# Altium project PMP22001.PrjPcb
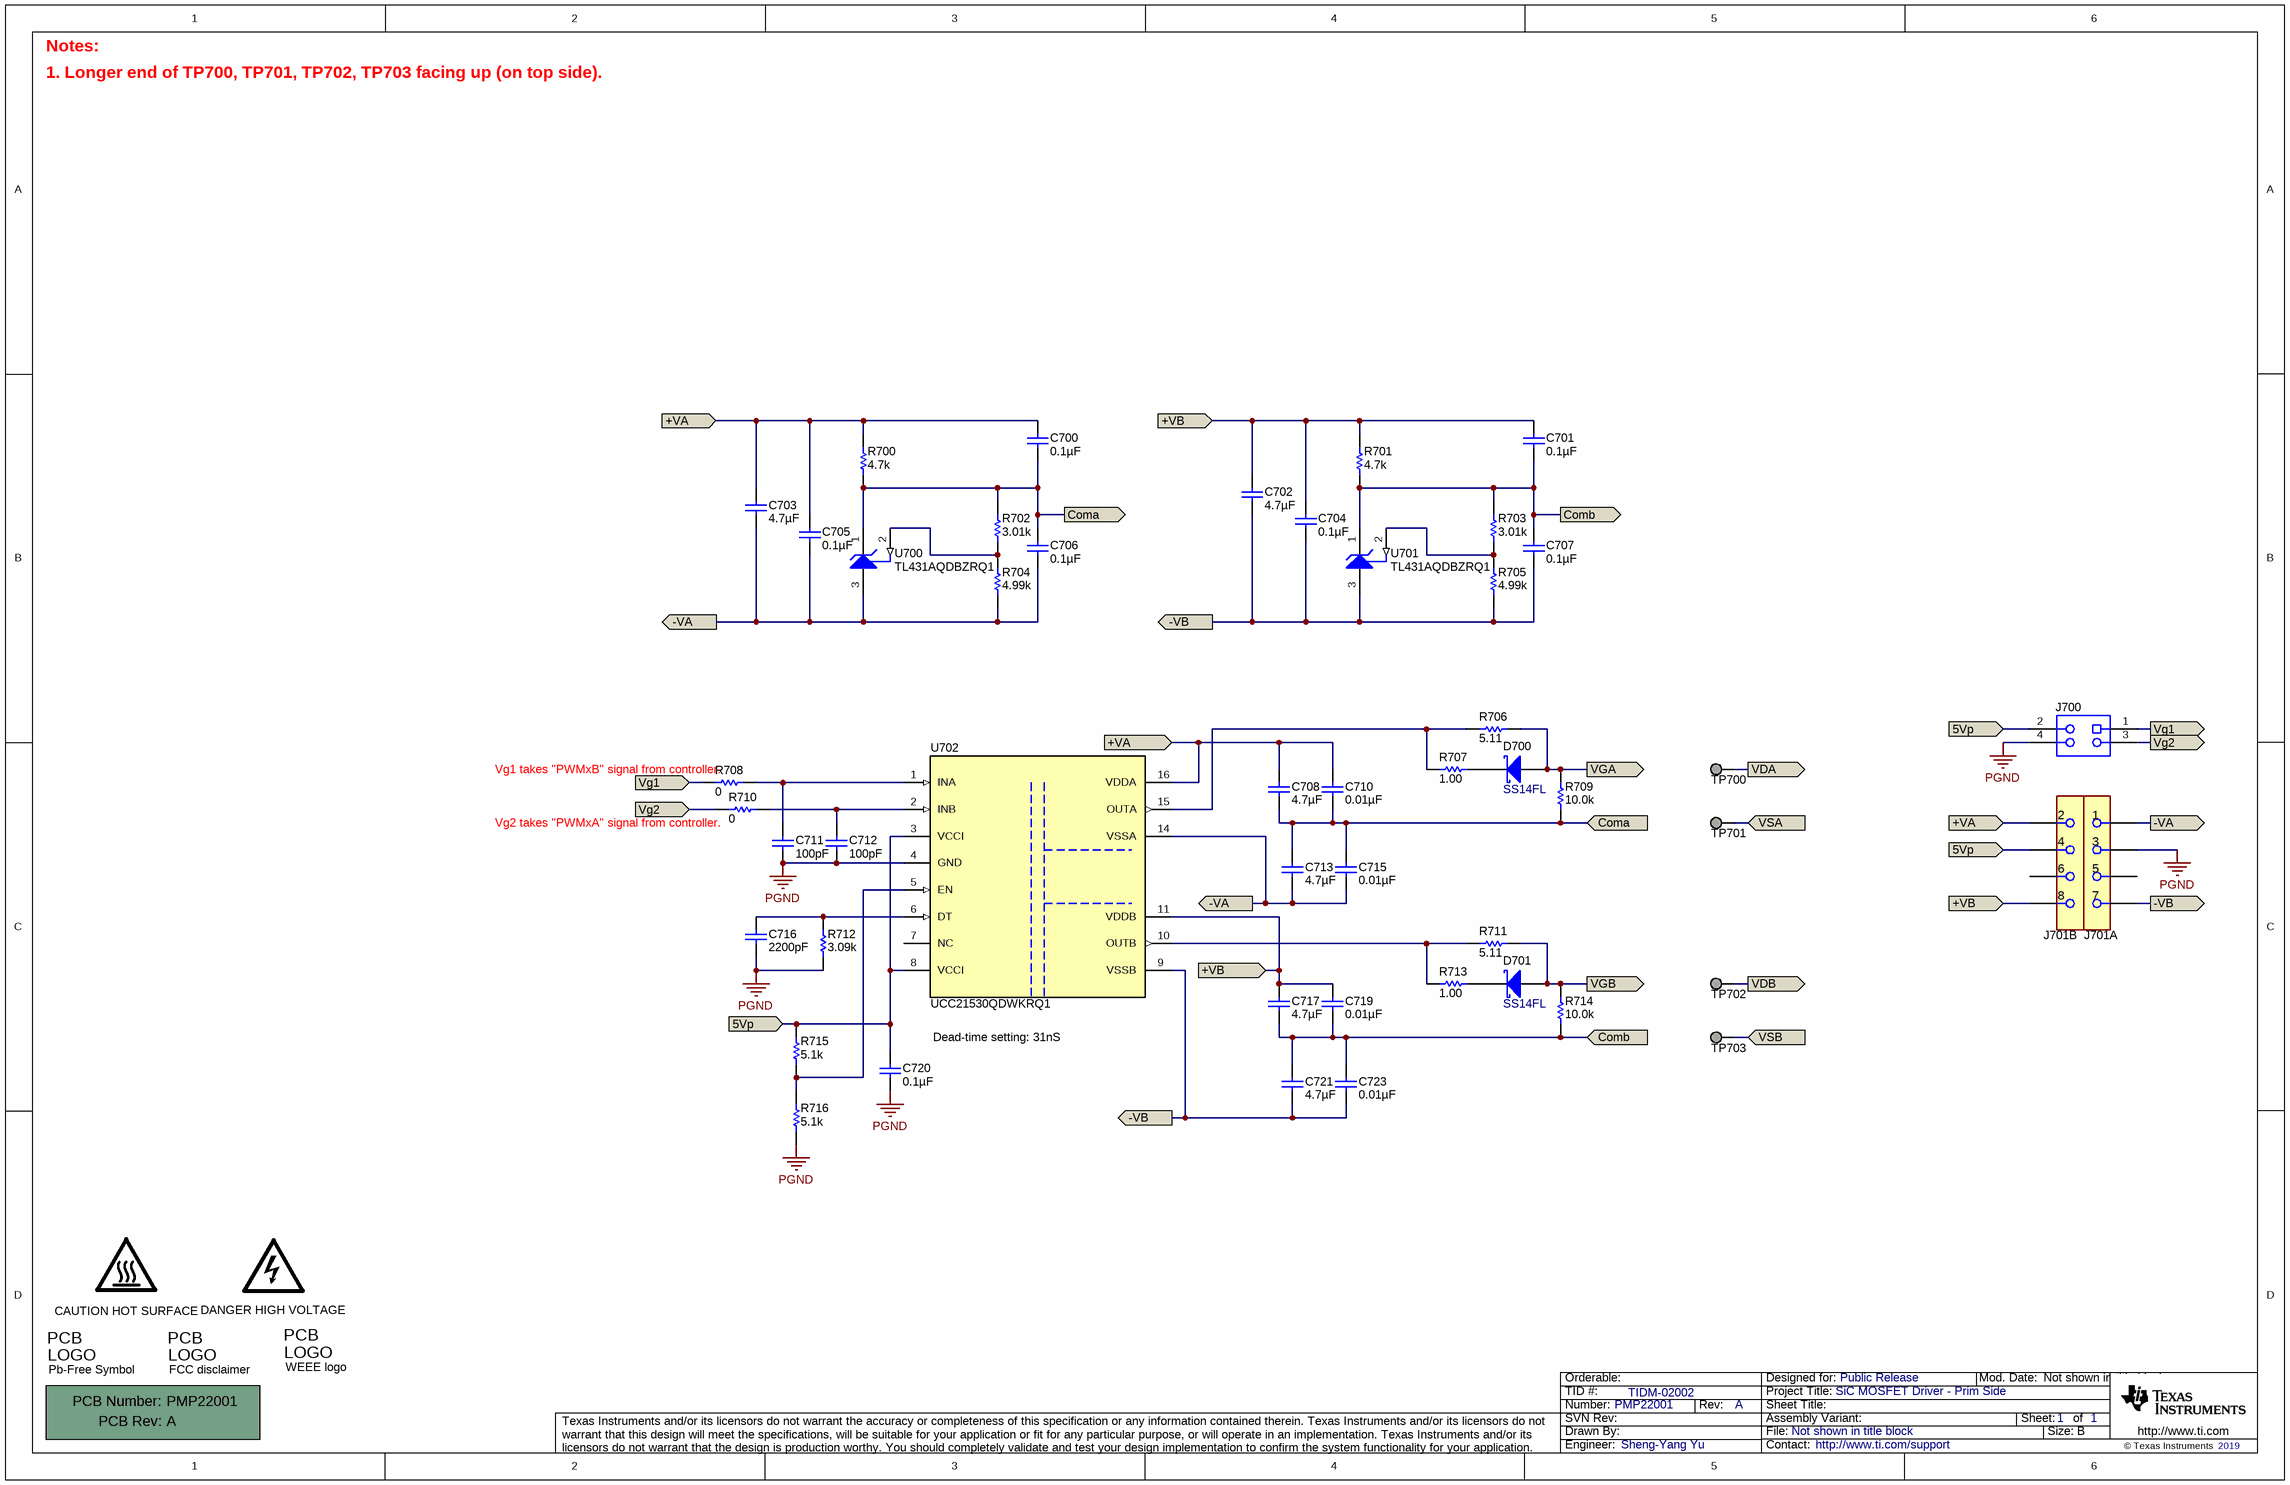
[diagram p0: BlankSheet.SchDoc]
CopyrightYear: 2019; PCB_Layout: Sheng-Yang Yu; PCB_Rev: A; PRJ_Customer: Public Release; PRJ_Engineer: Sheng-Yang Yu; PRJ_Number: PMP22001; PRJ_Title: SiC MOSFET Driver - Prim Side; SCH_Rev: A; TechSupport: http://www.ti.com/support; TID: TIDM-02002
1 sheet, 54 parts. Net scope: flat (ports and power ports of the same name join across sheets).
Board file: PCB.PcbDoc

## Sheet BlankSheet.SchDoc
size 431 x 279 mm; Date: Not shown in title block; ApprovedBy: Not shown in title block; CheckedBy: Not shown in title block; Author: Not shown in title block; CompanyName: Not shown in title block; Engineer: Not shown in title block; Organization: Not shown in title block; Address1: Not shown in title block; Address2: Not shown in title block; Address3: Not shown in title block; Address4: Not shown in title block; DocumentNumber: 1; Revision: Use project parameter SCH_Rev; SheetNumber: 1; SheetTotal: 1; PageSetup: Record=PageOptions¦CenterHorizontal=True¦CenterVertical=True¦PrintScale=1.00¦XCorrection=1.00¦YCorrection=1.00¦PrintKind=0¦BorderSize=5000000¦LeftOffset=0¦BottomOffset=0¦Orientation=2¦PaperLength=1000¦PaperWidth=1000¦Scale=100¦PaperSource=15¦PrintQuality=600¦MediaType=1¦DitherType=10¦PaperKind=Letter¦PrintScaleMode=1

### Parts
!PCB700  Printed Circuit Board  (value not drawn)  (mechanical)
C700  ValueDisplayed: 0.1µF  [0402]  (hidden comment: C1005X7R1H104K050BB)
C701  ValueDisplayed: 0.1µF  [0402]  (hidden comment: C1005X7R1H104K050BB)
C702  ValueDisplayed: 4.7µF  [0805_HV]  (hidden comment: CGA4J3X5R1H475K125AB)
C703  ValueDisplayed: 4.7µF  [0805_HV]  (hidden comment: CGA4J3X5R1H475K125AB)
C704  ValueDisplayed: 0.1µF  [0402]  (hidden comment: C1005X7R1H104K050BB)
C705  ValueDisplayed: 0.1µF  [0402]  (hidden comment: C1005X7R1H104K050BB)
C706  ValueDisplayed: 0.1µF  [0402]  (hidden comment: C1005X7R1H104K050BB)
C707  ValueDisplayed: 0.1µF  [0402]  (hidden comment: C1005X7R1H104K050BB)
C708  ValueDisplayed: 4.7µF  [0805_HV]  (hidden comment: CGA4J3X5R1H475K125AB)
C710  ValueDisplayed: 0.01µF  [0402]  (hidden comment: GRM155R71H103KA88D)
C711  ValueDisplayed: 100pF  [0402]  (hidden comment: 0402YC101KAT2A)
C712  ValueDisplayed: 100pF  [0402]  (hidden comment: 0402YC101KAT2A)
C713  ValueDisplayed: 4.7µF  [0805_HV]  (hidden comment: CGA4J3X5R1H475K125AB)
C715  ValueDisplayed: 0.01µF  [0402]  (hidden comment: GRM155R71H103KA88D)
C716  ValueDisplayed: 2200pF  [0402]  (hidden comment: 885012205027)
C717  ValueDisplayed: 4.7µF  [0805_HV]  (hidden comment: CGA4J3X5R1H475K125AB)
C719  ValueDisplayed: 0.01µF  [0402]  (hidden comment: GRM155R71H103KA88D)
C720  ValueDisplayed: 0.1µF  [0402]  (hidden comment: 0402YC104KAT2A)
C721  ValueDisplayed: 4.7µF  [0805_HV]  (hidden comment: CGA4J3X5R1H475K125AB)
C723  ValueDisplayed: 0.01µF  [0402]  (hidden comment: GRM155R71H103KA88D)
D700  SS14FL  [SOD-123F]
D701  SS14FL  [SOD-123F]
J700  CLT-102-02-G-D-BE  [Samtec_CLT-102-02-x-D-BE]  (value not drawn)
J701  CLT-104-02-G-D  [FP-CLT-104-02-G-D_HDR8-MFG]  (value not drawn)  (parts A,B of 2)
LOGO700  DANGER HIGH VOLTAGE  [IEC_HighVoltage_Small]  (no BOM)
LOGO704  CAUTION HOT SURFACE  [IEC_HotSurface_Small]  (no BOM)
Logo707  WEEE logo  [WEEE_Minimum]  (no BOM)
Logo708  Pb-Free Symbol  [Pb-Free_Overlay_Small]  (no BOM)
Logo709  FCC disclaimer  [FCC_disclaimer]  (no BOM)
R700  ValueDisplayed: 4.7k  [0805_HV]  (hidden comment: AC0805JR-074K7L)
R701  ValueDisplayed: 4.7k  [0805_HV]  (hidden comment: AC0805JR-074K7L)
R702  ValueDisplayed: 3.01k  [0402]  (hidden comment: CRCW04023K01FKED)
R703  ValueDisplayed: 3.01k  [0402]  (hidden comment: CRCW04023K01FKED)
R704  ValueDisplayed: 4.99k  [0402]  (hidden comment: CRCW04024K99FKED)
R705  ValueDisplayed: 4.99k  [0402]  (hidden comment: CRCW04024K99FKED)
R706  ValueDisplayed: 5.11  [0603]  (hidden comment: CRCW06035R11FKEA)
R707  ValueDisplayed: 1.00  [0603]  (hidden comment: RC0603FR-071RL)
R708  ValueDisplayed: 0  [0402]  (hidden comment: CRCW04020000Z0ED)
R709  ValueDisplayed: 10.0k  [0603]  (hidden comment: CRCW060310K0FKEA)
R710  ValueDisplayed: 0  [0402]  (hidden comment: CRCW04020000Z0ED)
R711  ValueDisplayed: 5.11  [0603]  (hidden comment: CRCW06035R11FKEA)
R712  ValueDisplayed: 3.09k  [0402]  (hidden comment: CRCW04023K09FKED)
R713  ValueDisplayed: 1.00  [0603]  (hidden comment: RC0603FR-071RL)
R714  ValueDisplayed: 10.0k  [0603]  (hidden comment: CRCW060310K0FKEA)
R715  ValueDisplayed: 5.1k  [0402]  (hidden comment: CRCW04025K10JNED)
R716  ValueDisplayed: 5.1k  [0402]  (hidden comment: CRCW04025K10JNED)
TP700  3104-2-00-34-00-00-08-0  [3104-2]  (value not drawn)
TP701  3104-2-00-34-00-00-08-0  [3104-2]  (value not drawn)
TP702  3104-2-00-34-00-00-08-0  [3104-2]  (value not drawn)
TP703  3104-2-00-34-00-00-08-0  [3104-2]  (value not drawn)
U700  TL431AQDBZRQ1  [DBZ0003A_N]
U701  TL431AQDBZRQ1  [DBZ0003A_N]
U702  UCC21530QDWKRQ1  [DWK0014A]

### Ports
5Vp (in), +VA (in), +VB (in), -VA (out), -VB (out), Coma (in), Coma (out), Comb (in), Comb (out), VDA (out), VDB (out), Vg1 (in), Vg1 (out), Vg2 (in), Vg2 (out), VGA (out), VGB (out), VSA (in), VSB (in)

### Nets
PGND: C711.2 C712.2 C716.2 C720.2 J700.4 J701.3 R712.1 R716.1 U702.4(GND)
5Vp: C720.1 J700.2 J701.4 R715.2 U702.3(VCCI) U702.8(VCCI) ; port 5Vp
+VA: C700.1 C703.1 C705.1 C708.1 C710.1 J701.2 R700.2 U702.16(VDDA) ; port +VA
+VB: C701.1 C702.1 C704.1 C717.1 C719.1 J701.8 R701.2 U702.11(VDDB) ; port +VB
-VA: C703.2 C705.2 C706.2 C713.2 C715.2 J701.1 R704.1 U700.3(ANODE) U702.14(VSSA) ; port -VA
-VB: C702.2 C704.2 C707.2 C721.2 C723.2 J701.7 R705.1 U701.3(ANODE) U702.9(VSSB) ; port -VB
Coma: C700.2 C706.1 C708.2 C710.2 C713.1 C715.1 R700.1 R702.2 R709.1 U700.1(CATHODE) ; port Coma
Comb: C701.2 C707.1 C717.2 C719.2 C721.1 C723.1 R701.1 R703.2 R714.1 U701.1(CATHODE) ; port Comb
VDA: TP700.1 ; port VDA
VDB: TP702.1 ; port VDB
Vg1: J700.1 R708.1 ; port Vg1
Vg2: J700.3 R710.1 ; port Vg2
VGA: D700.2(A) R706.2 R709.2 ; port VGA
VGB: D701.2(A) R711.2 R714.2 ; port VGB
VSA: TP701.1 ; port VSA
VSB: TP703.1 ; port VSB
NetC711_1: C711.1 R708.2 U702.1(INA)
NetC712_1: C712.1 R710.2 U702.2(INB)
NetC716_1: C716.1 R712.2 U702.6(DT)
NetD700_1: D700.1(K) R707.2
NetD701_1: D701.1(K) R713.2
NetR702_1: R702.1 R704.2 U700.2(REF)
NetR703_1: R703.1 R705.2 U701.2(REF)
NetR706_1: R706.1 R707.1 U702.15(OUTA)
NetR711_1: R711.1 R713.1 U702.10(OUTB)
NetR715_1: R715.1 R716.2 U702.5(EN)

Not connected (* = marked no-connect by the designer): J701 5 6; U702 7(NC)

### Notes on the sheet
- Notes:
- 1. Longer end of TP700, TP701, TP702, TP703 facing up (on top side).
- (near R708) Vg1 takes "PWMxB" signal from controller.
- (near R710) Vg2 takes "PWMxA" signal from controller.
- Dead-time setting: 31nS

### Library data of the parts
!PCB700 = CMP-0003618-2: Manufacturer: Any; PartNumber: PMP22001
C700 C701 C704-C707 = C1005X7R1H104K050BB: CAP, CERM, 0.1 µF, 50 V,+/- 10%, X7R, 0402; Manufacturer: TDK; Polarized: N; CompType: Capacitor; Value: 0.1uF; U/M: EA; Cap_F: 0.0000001; Tolerance_%: 10; ESR_ohm: 0.039064; Value1: 0.039064 ohm; VDC_V: 50; Value2: 50V; IRMS_A: 0.814669; TaMin_C: -55; TaMax_C: 125; SizeArea_mm2: 0.5; SizeAreaWB_mm2: 3; SizeX_mm: 1; SizeZ_mm: 0.6; AEC Category: Q200; Green_Lifecycle: NRND; Green_REACh: Passed
C702 C703 C708 C713 C717 C721 = GRT21BR61H475KE13L: CAP, CERM, 4.7 µF, 50 V,+/- 10%, X5R, AEC-Q200 Grade 3, 0805; Manufacturer: TDK; Polarized: N; CompType: Capacitor; Value: 4.7uF; U/M: EA; Cap_F: 0.0000047; Tolerance_%: 10; VDC_V: 50; Value2: 50V; TaMin_C: -55; TaMax_C: 85; Cap_Case: 0805; SizeArea_mm2: 2.5; SizeAreaWB_mm2: 6.75; SizeX_mm: 2; SizeY_mm: 1.25; SizeZ_mm: 1.45; AEC Category: Q200; AEC Qualified: Y; AEC Grade: 3
C710 C715 C719 C723 = GRM155R71H103KA88D: CAP, CERM, 0.01 µF, 50 V,+/- 10%, X7R, 0402; Manufacturer: MuRata; Polarized: N; CompType: Capacitor; Value: 0.01uF; U/M: EA; Cap_F: 0.00000001; Tolerance_%: 10; VDC_V: 50; Value2: 50V; TaMin_C: -55; TaMax_C: 125; SizeArea_mm2: 0.5; SizeAreaWB_mm2: 3; SizeX_mm: 1; SizeZ_mm: 0.6; AEC Category: Q200; Green_Lifecycle: Active; Green_REACh: Passed
C711 C712 = 0402YC101KAT2A: CAP, CERM, 100 pF, 16 V,+/- 10%, X7R, 0402; Manufacturer: AVX; Polarized: N; CompType: Capacitor; Value: 100pF; U/M: EA; Cap_F: 0.0000000001; Tolerance_%: 10; VDC_V: 16; Value2: 16V; TaMin_C: -55; TaMax_C: 125; SizeArea_mm2: 0.5; SizeAreaWB_mm2: 3; SizeX_mm: 1; SizeZ_mm: 0.6; AEC Category: Q200
C716 = 885012205027: CAP, CERM, 2200 pF, 16 V,+/- 10%, X7R, 0402; Manufacturer: Wurth Elektronik; Polarized: N; CompType: Capacitor; Value: 2200pF; U/M: EA; Cap_F: 0.0000000022; Tolerance_%: 10; VDC_V: 16; Value2: 16V; TaMin_C: -55; TaMax_C: 125; SizeArea_mm2: 0.5; SizeAreaWB_mm2: 3; SizeX_mm: 1; SizeZ_mm: 0.6; AEC Category: Q200
C720 = 0402YC104KAT2A: CAP, CERM, 0.1 µF, 16 V,+/- 10%, X7R, 0402; Manufacturer: AVX; Polarized: N; CompType: Capacitor; Value: 0.1uF; U/M: EA; Cap_F: 0.0000001; Tolerance_%: 10; VDC_V: 16; Value2: 16V; TaMin_C: -55; TaMax_C: 125; SizeArea_mm2: 0.5; SizeAreaWB_mm2: 3; SizeX_mm: 1; SizeZ_mm: 0.6; AEC Category: Q200; Green_Lifecycle: Active; Green_REACh: Passed
D700 D701 = CMP-0028801-2: Diode, Schottky, 40 V, 1 A, AEC-Q101, SOD-123F; Manufacturer: Fairchild Semiconductor; Value1: 1A; SizeX_mm: 3.5; Vr_V: 40V; Value2: 0.55V; AEC Category: Q101; Vf_V: 550mV; SizeArea_mm2: 5.6; SizeZ_mm: 1.1; Value: 40V; AEC Qualified: Y; SizeAreaWB_mm2: 11.7; SizeY_mm: 1.6; TJmax_C: 125°C; Green_REACh: Incomplete; Green_Lifecycle: Not Set
J700 = CMP-0082275-1: Receptacle, 2mm, 2x2, Gold, SMT; Manufacturer: Samtec; Pitch_mm: 2; Gender: Female; Cert_UL: Y; Current_A: 4.1A; CompType: Socket Strip
J701 = CMP-0086478-1: CONN RCPT 8POS 0.079 GOLD SMD; Manufacturer: Samtec; Row_Count: 2; ContactFinish: Gold,Nickel; Current_A: 4.1A; Symbol Name: SYM-CLT-104-02-G-D
LOGO700 = IEC_HighVoltage: IEC 61010-1 High Voltage Warning; SymbolCreator: a0412235
LOGO704 = IEC_HotSurface: IEC 61010-1 Hot Surface Warning; SymbolCreator: a0412235
Logo707 = CMP-0074769-1
Logo708 = CMP-0074839-1: SymbolCreator: a0412235; Library Reference: Logo
Logo709 = CMP-0074847-1: FCC_disclaimer; Library Reference: Logo
R700 R701 = CRCW08054K70JNEA: RES, 4.7 k, 5%, 0.125 W, 0805; Manufacturer: Yageo America; CompType: Resistor; Value: 4.7k; Res_ohm: 4700; Value_Code: 4k70; Tolerance_%: 5; Power_W: 0.125; Value2: 0.125W; VDC_V: 150; TempCo: 200 ppm/C; SizeArea_mm2: 2.5; SizeX_mm: 2; SizeY_mm: 1.25; SizeZ_mm: 1.45; EIA_Code: E24; U/M: EA; AEC Category: Q200; Green_Lifecycle: Active; Green_REACh: Passed
R702 R703 = CRCW04023K01FKED: RES, 3.01 k, 1%, 0.063 W, 0402; Manufacturer: Vishay-Dale; CompType: Resistor; Value: 3.01k; Res_ohm: 3010; Value_Code: 3k01; Tolerance_%: 1; Power_W: 0.063; Value2: 0.063W; VDC_V: 50; TempCo: 100 ppm/C; SizeArea_mm2: 0.5; SizeZ_mm: 0.6; EIA_Code: E96; U/M: EA; AEC Category: Q200; Green_Lifecycle: Active; Green_REACh: Passed
R704 R705 = CRCW04024K99FKED: RES, 4.99 k, 1%, 0.063 W, 0402; Manufacturer: Vishay-Dale; CompType: Resistor; Value: 4.99k; Res_ohm: 4990; Value_Code: 4k99; Tolerance_%: 1; Power_W: 0.063; Value2: 0.063W; VDC_V: 50; TempCo: 100 ppm/C; SizeArea_mm2: 0.5; SizeZ_mm: 0.6; EIA_Code: E96; U/M: EA; AEC Category: Q200; Green_Lifecycle: Active; Green_REACh: Passed
R706 R711 = CRCW06035R11FKEA: RES, 5.11, 1%, 0.1 W, 0603; Manufacturer: Vishay-Dale; CompType: Resistor; Value: 5.11; Value_Code: 5R11; Tolerance_%: 1; Power_W: 0.1; Value2: 0.1W; VDC_V: 75; TempCo: 100 ppm/C; SizeArea_mm2: 1.28; SizeX_mm: 1.6; SizeY_mm: 0.8; EIA_Code: E96; U/M: EA; AEC Category: Q200; Green_Lifecycle: Active; Green_REACh: Passed
R707 R713 = RC0603FR-071RL: RES, 1.00, 1%, 0.1 W, 0603; Manufacturer: Yageo America; CompType: Resistor; Value: 1.00; Res_ohm: 1; Value_Code: 1R00; Power_W: 0.1; Value2: 0.1W; VDC_V: 150; TempCo: 200 ppm/C; SizeArea_mm2: 1.28; SizeX_mm: 1.6; SizeY_mm: 0.8; EIA_Code: E96; U/M: EA; AEC Category: Q200; Green_Lifecycle: Active; Green_REACh: Passed
R708 R710 = CRCW04020000Z0ED: RES, 0, 5%, 0.063 W, 0402; Manufacturer: Vishay-Dale; CompType: Resistor; Value: 0; Value_Code: 0000; Tolerance_%: 5; Power_W: 0.063; Value2: 0.063W; VDC_V: 50; TempCo: 200 ppm/C; SizeArea_mm2: 0.5; SizeX_mm: 1; SizeZ_mm: 0.6; EIA_Code: E24; U/M: EA; AEC Category: Q200; Green_Lifecycle: Active; Green_REACh: Passed
R709 R714 = CRCW060310K0FKEA: RES, 10.0 k, 1%, 0.1 W, 0603; Manufacturer: Vishay-Dale; CompType: Resistor; Value: 10.0k; Res_ohm: 10000; Value_Code: 10k0; Tolerance_%: 1; Power_W: 0.1; Value2: 0.1W; VDC_V: 75; TempCo: 100 ppm/C; SizeArea_mm2: 1.28; SizeX_mm: 1.6; SizeY_mm: 0.8; EIA_Code: E96; U/M: EA; AEC Category: Q200; Green_Lifecycle: Active; Green_REACh: Passed
R712 = CRCW04023K09FKED: RES, 3.09 k, 1%, 0.063 W, 0402; Manufacturer: Vishay-Dale; CompType: Resistor; Value: 3.09k; Res_ohm: 3090; Value_Code: 3k09; Tolerance_%: 1; Power_W: 0.063; Value2: 0.063W; VDC_V: 50; TempCo: 100 ppm/C; SizeArea_mm2: 0.5; SizeZ_mm: 0.6; EIA_Code: E96; U/M: EA; AEC Category: Q200; Green_Lifecycle: Active; Green_REACh: Passed
R715 R716 = CRCW04025K10JNED: RES, 5.1 k, 5%, 0.063 W, 0402; Manufacturer: Vishay-Dale; CompType: Resistor; Value: 5.1k; Res_ohm: 5100; Value_Code: 5k10; Tolerance_%: 5; Power_W: 0.063; Value2: 0.063W; VDC_V: 50; TempCo: 200 ppm/C; SizeArea_mm2: 0.5; SizeX_mm: 1; SizeZ_mm: 0.6; EIA_Code: E24; U/M: EA; AEC Category: Q200; Green_Lifecycle: Active; Green_REACh: Passed
TP700-TP703 = CMP-0055001-1: PCB Pin, Swage Mount, TH; Manufacturer: Mill-Max; CNHeader: FALSE; Green_Lifecycle: Active; Green_REACh: Passed; CompType: PCB Pin
U700 U701 = TL431AQDBZRQ1: Automotive Catalog Adjustable Precision Shunt Regulator, 34 ppm / degC, 100 mA, -40 to 125 degC, 3-pin SOT-23 (DBZ), Green (RoHS & no Sb/Br); Manufacturer: Texas Instruments; Alternate PartNumber: Equivalent; Initial Accuracy @ 25/deg C(%): 1; Iout/Iz(Max)(mA): 100; Min Iz for Regulation(uA): 600; SubFamily: Shunt Voltage Reference; Temp Coeff(Typ)(ppm/ degree C): 34; VO Adj(Max)(V): 36; VO Adj(Min)(V): 2.495
U702 = CMP-0083997-1: 4-A, 6-A, 5.7-kVRMS Isolated Dual-Channel Gate Driver with Enable, DWK0014A (SOIC-14); Alternate PartNumber: UCC21530QDWKQ1; Alternate Manufacturer: Texas Instruments; SizeAreaWB_mm2: 151.29; SizeZ_mm: 2.65; SizeX_mm: 10.3; SizeArea_mm2: 106.09; CompType: IC; AEC Qualified: Y; AEC Category: Q200

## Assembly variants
001: all parts fitted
